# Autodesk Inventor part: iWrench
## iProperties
Shininess: 64.0
Length Units: 11272
Angle Units: 11279
Time Units: 11290
Mass Units: 11286
Length Display Precision: 3
Angle Display Precision: 2
Compacted: True
Part Number: iWrench
Document SubType Name: Modeling
Created: 2003-01
Designer: Charles Bliss
Density: 0.0
Volumn: 0.0
Area: 0.0
PropertySet Name: Model Information
Control State: 0
Master: False
Checked Out: False
Author: Charles Bliss
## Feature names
1. Extrusion1
2. Revolution1
3. Extrusion2
4. Fillet1
5. Extrusion3
6. Fillet2
7. Extrusion4
